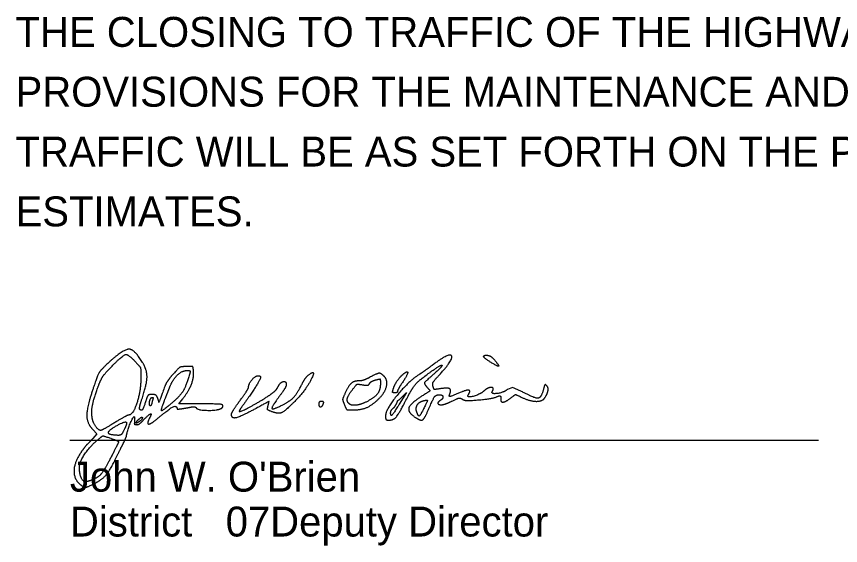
# Model space of a CAD drawing. Extents: x 0 to 34, y 0 to 22.
# Drawn here: x 26.158 to 30.011, y 2.884 to 5.359 of the extents above; entities that cross this region are included whole.
import ezdxf

# ---------------------------------------------------------------- set-up
doc = ezdxf.new("R2010")
doc.units = 0
doc.layers.add('SH_Data', color=7, linetype='Continuous')
doc.layers.add('SH_Text', color=7, linetype='Continuous')

msp = doc.modelspace()

# ---------------------------------------------------------------- linework, layer by layer
at = {"layer": 'SH_Data'}
msp.add_line((26.408, 3.376), (29.908, 3.376), dxfattribs=at)
at = {"layer": 'SH_Text'}
msp.add_line((28.3734, 3.7423), (28.3734, 3.7423), dxfattribs=at)
for points in [[(28.5161, 3.6063), (28.4772, 3.6229), (28.4541, 3.6144)], [(27.9486, 3.567), (27.982, 3.6002), (27.9474, 3.5453)], [(27.0205, 3.5464), (26.9176, 3.5464), (26.9359, 3.5704)], [(26.5148, 3.427), (26.5342, 3.4064), (26.5148, 3.3846)]]:
    msp.add_lwpolyline(points, dxfattribs=at)
for points in [[(26.7477, 3.7399), (26.7106, 3.8009), (26.6612, 3.804), (26.6, 3.7493)], [(26.602, 3.7204), (26.6559, 3.7757), (26.6801, 3.7801), (26.7162, 3.7415)], [(26.6, 3.7493), (26.5538, 3.7079), (26.5361, 3.679), (26.512, 3.6054)], [(26.7162, 3.7415), (26.7366, 3.7197), (26.7394, 3.7107), (26.7394, 3.6675)], [(26.7465, 3.5755), (26.7681, 3.6395), (26.7686, 3.7057), (26.7477, 3.7399)], [(28.1331, 3.68), (28.2026, 3.7548), (28.1824, 3.7876), (28.1034, 3.7283)], [(28.3734, 3.7423), (28.3471, 3.7583), (28.3389, 3.7746), (28.3574, 3.7741)], [(28.3574, 3.7741), (28.3689, 3.7738), (28.3865, 3.7606), (28.4023, 3.7404)], [(28.4023, 3.7404), (28.4168, 3.7219), (28.4055, 3.7227), (28.3734, 3.7423)], [(26.5396, 3.6264), (26.5521, 3.6605), (26.5702, 3.6877), (26.602, 3.7204)], [(26.8756, 3.6275), (26.8882, 3.6597), (26.9321, 3.7024), (26.9527, 3.7024)], [(26.9525, 3.7214), (26.9266, 3.7206), (26.9165, 3.7147), (26.8907, 3.6856)], [(26.9858, 3.698), (26.9835, 3.7208), (26.9813, 3.7223), (26.9525, 3.7214)], [(26.9527, 3.7024), (26.9695, 3.7024), (26.9716, 3.6997), (26.967, 3.6844)], [(27.9969, 3.5971), (28.0139, 3.6298), (28.0533, 3.6678), (28.1134, 3.7094)], [(28.1034, 3.7283), (28.0814, 3.7118), (28.0526, 3.6913), (28.0394, 3.6829)], [(28.1134, 3.7094), (28.149, 3.7341), (28.1462, 3.718), (28.1094, 3.686)], [(26.7394, 3.6675), (26.7394, 3.6076), (26.7026, 3.4944), (26.6832, 3.4944)], [(26.8907, 3.6856), (26.8737, 3.6665), (26.8561, 3.6408), (26.8516, 3.6286)], [(26.967, 3.6844), (26.9501, 3.6285), (26.9256, 3.5866), (26.8931, 3.5581)], [(26.9359, 3.5704), (26.9635, 3.6065), (26.9884, 3.6704), (26.9858, 3.698)], [(27.2994, 3.6712), (27.2994, 3.6633), (27.2587, 3.5984), (27.22, 3.5444)], [(27.2434, 3.6264), (27.2434, 3.6414), (27.2751, 3.6784), (27.2879, 3.6784)], [(27.2879, 3.6784), (27.2942, 3.6784), (27.2994, 3.6751), (27.2994, 3.6712)], [(27.5201, 3.679), (27.563, 3.7146), (27.5091, 3.6082), (27.4589, 3.558)], [(27.4912, 3.6358), (27.5007, 3.6542), (27.5137, 3.6736), (27.5201, 3.679)], [(27.8093, 3.6704), (27.7929, 3.6616), (27.7721, 3.6544), (27.7631, 3.6544)], [(27.8778, 3.6748), (27.8621, 3.6905), (27.8447, 3.6894), (27.8093, 3.6704)], [(27.8374, 3.6586), (27.8577, 3.6637), (27.8594, 3.6623), (27.8594, 3.6399)], [(27.8588, 3.5778), (27.883, 3.6035), (27.8938, 3.6588), (27.8778, 3.6748)], [(28.0394, 3.6829), (27.9895, 3.6509), (27.8834, 3.519), (27.8834, 3.4889)], [(27.9199, 3.6164), (27.9263, 3.6372), (27.9493, 3.6714), (27.9663, 3.6855)], [(27.9663, 3.6855), (27.9882, 3.7037), (27.9862, 3.6818), (27.9628, 3.6469)], [(28.1094, 3.686), (28.0681, 3.6501), (28.0633, 3.6401), (28.0793, 3.6224)], [(28.1054, 3.6291), (28.1023, 3.6408), (28.1103, 3.6555), (28.1331, 3.68)], [(26.5129, 3.477), (26.5073, 3.5062), (26.5185, 3.5689), (26.5396, 3.6264)], [(26.8516, 3.6286), (26.8229, 3.5511), (26.8251, 3.5547), (26.8182, 3.5733)], [(26.8523, 3.5684), (26.8615, 3.5915), (26.872, 3.6181), (26.8756, 3.6275)], [(27.2034, 3.5624), (27.2254, 3.5922), (27.2434, 3.621), (27.2434, 3.6264)], [(27.3295, 3.5795), (27.3527, 3.5943), (27.3758, 3.6154), (27.3808, 3.6264)], [(27.3808, 3.6264), (27.3903, 3.6472), (27.4194, 3.6543), (27.4194, 3.6358)], [(27.4194, 3.6358), (27.4194, 3.63), (27.4049, 3.6059), (27.3873, 3.5823)], [(27.4004, 3.541), (27.4386, 3.5606), (27.4686, 3.592), (27.4912, 3.6358)], [(27.7631, 3.6544), (27.7372, 3.6544), (27.7108, 3.6326), (27.6954, 3.5985)], [(27.7284, 3.6125), (27.7469, 3.6367), (27.7528, 3.6396), (27.7763, 3.6358)], [(27.7763, 3.6358), (27.7943, 3.6329), (27.8052, 3.635), (27.8093, 3.6423)], [(27.8594, 3.6399), (27.8594, 3.6104), (27.8298, 3.5732), (27.7923, 3.5553)], [(27.8093, 3.6423), (27.8126, 3.6482), (27.8253, 3.6556), (27.8374, 3.6586)], [(27.9628, 3.6469), (27.9499, 3.6277), (27.9394, 3.6089), (27.9394, 3.6052)], [(28.0793, 3.6224), (28.092, 3.6084), (28.0915, 3.6069), (28.07, 3.5935)], [(28.1385, 3.6173), (28.1141, 3.6134), (28.109, 3.6152), (28.1054, 3.6291)], [(28.3834, 3.6064), (28.3935, 3.6228), (28.3623, 3.6241), (28.345, 3.608)], [(28.6368, 3.6321), (28.6307, 3.6382), (28.6266, 3.634), (28.6226, 3.6175)], [(28.6277, 3.5744), (28.6413, 3.5953), (28.6457, 3.6232), (28.6368, 3.6321)], [(26.512, 3.6054), (26.486, 3.5262), (26.4871, 3.4564), (26.5148, 3.427)], [(26.7922, 3.5904), (26.7766, 3.5904), (26.7707, 3.5843), (26.763, 3.5604)], [(26.8182, 3.5733), (26.8141, 3.5844), (26.805, 3.5904), (26.7922, 3.5904)], [(27.6954, 3.5985), (27.6833, 3.5717), (27.6827, 3.5633), (27.6913, 3.5427)], [(27.7127, 3.5477), (27.7016, 3.5588), (27.7081, 3.5859), (27.7284, 3.6125)], [(27.898, 3.4704), (27.9225, 3.4704), (27.9477, 3.5026), (27.9969, 3.5971)], [(27.9268, 3.5984), (27.9175, 3.5984), (27.9157, 3.603), (27.9199, 3.6164)], [(27.9394, 3.6052), (27.9394, 3.6014), (27.9337, 3.5984), (27.9268, 3.5984)], [(28.07, 3.5935), (28.0026, 3.5516), (27.9843, 3.5087), (28.0231, 3.4833)], [(28.0881, 3.5285), (28.1067, 3.5718), (28.1172, 3.587), (28.1301, 3.5889)], [(28.1301, 3.5889), (28.148, 3.5916), (28.1549, 3.5719), (28.1394, 3.5624)], [(28.1846, 3.5947), (28.1918, 3.6134), (28.1727, 3.6227), (28.1385, 3.6173)], [(28.2412, 3.6029), (28.1893, 3.5816), (28.179, 3.5801), (28.1846, 3.5947)], [(28.2707, 3.5893), (28.2816, 3.607), (28.2673, 3.6135), (28.2412, 3.6029)], [(28.345, 3.608), (28.3255, 3.5899), (28.261, 3.5736), (28.2707, 3.5893)], [(28.3364, 3.5669), (28.3885, 3.5718), (28.4271, 3.5913), (28.422, 3.5664)], [(28.4541, 3.6144), (28.4327, 3.598), (28.3743, 3.5916), (28.3834, 3.6064)], [(28.4701, 3.5748), (28.4906, 3.5909), (28.4917, 3.591), (28.5212, 3.5769)], [(28.6226, 3.6175), (28.6121, 3.5747), (28.5809, 3.5714), (28.5161, 3.6063)], [(26.7346, 3.5205), (26.7319, 3.5232), (26.7372, 3.548), (26.7465, 3.5755)], [(26.763, 3.5604), (26.7524, 3.5271), (26.7422, 3.5128), (26.7346, 3.5205)], [(26.7794, 3.5499), (26.7794, 3.554), (26.7799, 3.5596), (26.7864, 3.5743)], [(26.792, 3.554), (26.7879, 3.5367), (26.7794, 3.5384), (26.7794, 3.5499)], [(26.7864, 3.5743), (26.7999, 3.5809), (26.7932, 3.5619), (26.792, 3.554)], [(26.8931, 3.5581), (26.8422, 3.5132), (26.8314, 3.5159), (26.8523, 3.5684)], [(27.1234, 3.5372), (27.1234, 3.5436), (27.0923, 3.5464), (27.0205, 3.5464)], [(27.1634, 3.4973), (27.1634, 3.5033), (27.1814, 3.5326), (27.2034, 3.5624)], [(27.1997, 3.5104), (27.208, 3.5104), (27.2882, 3.5531), (27.3295, 3.5795)], [(27.3347, 3.5386), (27.3396, 3.5581), (27.338, 3.5577), (27.2729, 3.5225)], [(27.4589, 3.558), (27.413, 3.5122), (27.3825, 3.4985), (27.352, 3.5101)], [(27.3873, 3.5823), (27.3501, 3.5325), (27.3549, 3.5176), (27.4004, 3.541)], [(27.584, 3.5584), (27.5771, 3.5584), (27.5714, 3.5527), (27.5714, 3.5457)], [(27.5714, 3.5457), (27.5714, 3.5316), (27.5886, 3.534), (27.5935, 3.5489)], [(27.5935, 3.5489), (27.5953, 3.5541), (27.591, 3.5584), (27.584, 3.5584)], [(27.7923, 3.5553), (27.7644, 3.5421), (27.7223, 3.5381), (27.7127, 3.5477)], [(27.7353, 3.5184), (27.7727, 3.5184), (27.828, 3.545), (27.8588, 3.5778)], [(27.9474, 3.5453), (27.9211, 3.5014), (27.9074, 3.487), (27.9074, 3.5037)], [(27.9194, 3.5264), (27.926, 3.5319), (27.9314, 3.5412), (27.9347, 3.5464)], [(27.9347, 3.5464), (27.9385, 3.5531), (27.9391, 3.562), (27.9486, 3.567)], [(28.0301, 3.5069), (28.0231, 3.525), (28.0393, 3.5555), (28.0587, 3.5605)], [(28.0587, 3.5605), (28.079, 3.5658), (28.0795, 3.5593), (28.0614, 3.5229)], [(28.1394, 3.5624), (28.1267, 3.5546), (28.1301, 3.5424), (28.1448, 3.5424)], [(28.1448, 3.5424), (28.1523, 3.5424), (28.1743, 3.5501), (28.1939, 3.5596)], [(28.1939, 3.5596), (28.2214, 3.5729), (28.2327, 3.5749), (28.2435, 3.5681)], [(28.2435, 3.5681), (28.2533, 3.562), (28.2812, 3.5616), (28.3364, 3.5669)], [(28.422, 3.5664), (28.4224, 3.5532), (28.4479, 3.5573), (28.4701, 3.5748)], [(28.5212, 3.5769), (28.5586, 3.5591), (28.6169, 3.5577), (28.6277, 3.5744)], [(26.8125, 3.4741), (26.8465, 3.5027), (26.9065, 3.5469), (26.9097, 3.5216)], [(26.9097, 3.5216), (26.9238, 3.5229), (26.9485, 3.5267), (26.9645, 3.5299)], [(26.9645, 3.5299), (26.983, 3.5337), (26.9955, 3.5326), (26.9989, 3.5271)], [(26.9989, 3.5271), (27.0046, 3.5179), (27.0892, 3.515), (27.1107, 3.5232)], [(27.1107, 3.5232), (27.1177, 3.5259), (27.1234, 3.5322), (27.1234, 3.5372)], [(27.2729, 3.5225), (27.2059, 3.4863), (27.1634, 3.4765), (27.1634, 3.4973)], [(27.22, 3.5444), (27.2066, 3.5257), (27.1975, 3.5104), (27.1997, 3.5104)], [(27.352, 3.5101), (27.3334, 3.5172), (27.3305, 3.5219), (27.3347, 3.5386)], [(27.6913, 3.5427), (27.7002, 3.521), (27.705, 3.5184), (27.7353, 3.5184)], [(27.9074, 3.5037), (27.9074, 3.5107), (27.9128, 3.5209), (27.9194, 3.5264)], [(28.0614, 3.5229), (28.046, 3.4921), (28.0374, 3.4877), (28.0301, 3.5069)], [(28.0531, 3.4705), (28.0587, 3.4705), (28.0745, 3.4966), (28.0881, 3.5285)], [(26.5527, 3.4224), (26.542, 3.4224), (26.5167, 3.4572), (26.5129, 3.477)], [(26.6832, 3.4944), (26.6792, 3.4944), (26.6493, 3.4782), (26.6166, 3.4584)], [(26.6721, 3.3942), (26.6752, 3.4232), (26.7162, 3.5126), (26.7085, 3.4519)], [(26.7085, 3.4519), (26.722, 3.447), (26.737, 3.4554), (26.751, 3.4699)], [(26.7404, 3.4698), (26.7261, 3.4591), (26.7131, 3.4536), (26.7211, 3.4655)], [(26.7211, 3.4655), (26.7237, 3.4692), (26.7284, 3.4732), (26.7346, 3.4783)], [(26.7346, 3.4783), (26.7448, 3.4887), (26.7479, 3.4777), (26.7404, 3.4698)], [(26.751, 3.4699), (26.7774, 3.4976), (26.7921, 3.5021), (26.7796, 3.4789)], [(26.7796, 3.4789), (26.7661, 3.4536), (26.7849, 3.4508), (26.8125, 3.4741)], [(27.8834, 3.4889), (27.8834, 3.4763), (27.888, 3.4704), (27.898, 3.4704)], [(28.0231, 3.4833), (28.0339, 3.4762), (28.0474, 3.4704), (28.0531, 3.4705)], [(26.6166, 3.4584), (26.584, 3.4386), (26.5552, 3.4224), (26.5527, 3.4224)], [(26.5891, 3.4156), (26.5926, 3.4261), (26.6662, 3.4663), (26.6717, 3.4607)], [(26.6717, 3.4607), (26.6741, 3.4583), (26.6698, 3.4433), (26.6622, 3.4274)], [(26.5396, 3.3802), (26.5608, 3.3975), (26.5627, 3.3976), (26.5984, 3.3855)], [(26.6319, 3.3993), (26.6035, 3.4009), (26.5864, 3.4074), (26.5891, 3.4156)], [(26.6622, 3.4274), (26.6526, 3.4071), (26.6434, 3.3987), (26.6319, 3.3993)], [(26.6594, 3.3657), (26.6629, 3.3707), (26.666, 3.3813), (26.6721, 3.3942)], [(26.4546, 3.2662), (26.4603, 3.2889), (26.5111, 3.3571), (26.5396, 3.3802)], [(26.4864, 3.3546), (26.4815, 3.3501), (26.468, 3.332), (26.4564, 3.3145)], [(26.5148, 3.3846), (26.5041, 3.3726), (26.4913, 3.3591), (26.4864, 3.3546)], [(26.5984, 3.3855), (26.6187, 3.3785), (26.6354, 3.3711), (26.6354, 3.3688)], [(26.6354, 3.3688), (26.6354, 3.3666), (26.6207, 3.3366), (26.6027, 3.302)], [(26.6293, 3.3051), (26.642, 3.332), (26.6564, 3.3588), (26.6594, 3.3657)], [(26.4564, 3.3145), (26.4255, 3.2677), (26.4288, 3.1871), (26.4626, 3.1645)], [(26.6027, 3.302), (26.5682, 3.2356), (26.5393, 3.2011), (26.5088, 3.1894)], [(26.5228, 3.1741), (26.5604, 3.1933), (26.5986, 3.2402), (26.6293, 3.3051)], [(26.4792, 3.1824), (26.4656, 3.1824), (26.4484, 3.2413), (26.4546, 3.2662)], [(26.4626, 3.1645), (26.4766, 3.1552), (26.4899, 3.1573), (26.5228, 3.1741)], [(26.5088, 3.1894), (26.4987, 3.1856), (26.4853, 3.1824), (26.4792, 3.1824)]]:
    msp.add_open_spline(points, degree=2, dxfattribs=at)

# ---------------------------------------------------------------- texts
at = {"layer": 'SH_Data'}
for s, p in [('THE CLOSING TO TRAFFIC OF THE HIGHWAY AND THAT', (26.1538, 5.2171)), ('PROVISIONS FOR THE MAINTENANCE AND SAFETY OF', (26.1538, 4.9371)), ('TRAFFIC WILL BE AS SET FORTH ON THE PLANS AND', (26.1538, 4.6571)), ('ESTIMATES.', (26.1538, 4.3771))]:
    msp.add_text(s, height=0.14, dxfattribs=at).set_placement(p)
at = {"layer": 'SH_Text'}
for s, p in [("John W. O'Brien", (26.408, 3.136)), ('District       Deputy Director', (26.408, 2.926)), ('              07', (26.408, 2.926))]:
    msp.add_text(s, height=0.14, dxfattribs=at).set_placement(p)

doc.saveas('drawing.dxf')
